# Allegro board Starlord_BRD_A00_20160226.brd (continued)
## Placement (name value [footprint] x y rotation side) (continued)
HS2  STFSR158R113H62-GP  [STFSR158R113H62]  174.7 89.86 0 top
HS3  STFSR158R113H62-GP  [STFSR158R113H62]  174.7 75.98 0 top
IOBD1  IPEX-CON50-1-GP  [20455-050E-76]  171.7 46.46 270 bottom
KBBD1  STAR-CON44-GP  [51540-04401-W01]  139.3 14.97 180 bottom
KBC24  MEC1404-NU-D0-1-GP-U  [TQFP128J16H48]  191.01 36.44 270 top
LCD1  IPEX-CON40-3-GP  [20455-040E-12]  88.7 97.71 0 bottom
NOREF  -  [unnamed]  69.91 -7.48 0 top
NOREF#2  -  [unnamed]  207.95 -120.53 0 top
NOREF#3  *  [unnamed]  232.84 113.08 0 top
NOREF#4  *  [unnamed]  196.87 17.19 0 top
NOREF#5  -  [#2]  160.17 12.82 0 top
NOREF#6  -  [unnamed]  169.35 102.57 0 top
NOREF#7  -  [#2]  1.7 -16.29 0 top
NOREF#8  -  [#2]  8.38 114.65 180 top
NOREF#9  -  [unnamed]  234.17 -121.61 0 top
NOREF#10  -  [unnamed]  234.17 78.88 0 top
NOREF#11  -  [#2]  -24.49 -18.4 0 top
NOREF#12  *  [unnamed]  24.59 91.1 0 top
NOREF#13  *  [unnamed]  175.84 37.13 0 top
NOREF#14  -  [#2]  130.55 110.71 0 top
NOREF#15  -  [#2]  1.7 -16.29 0 top
NOREF#16  -  [unnamed]  162.44 -4.62 0 top
NOREF#17  -  [unnamed]  24.4 108.43 180 top
NOREF#18  -  [#2]  72.4 113.39 180 top
NOREF#19  -  [#2]  5.44 -59.82 180 top
NOREF#20  *  [unnamed]  18.76 109.51 0 top
NOREF#21  -  [#2]  218.92 -126.91 0 top
NOREF#22  -  [#2]  57.65 -94.26 180 top
NOREF#23  *  [unnamed]  199.82 8.25 0 top
NOREF#24  -  [#2]  1.7 -16.29 0 top
NOREF#25  -  [unnamed]  -1.22 -25.43 0 top
NOREF#26  -  [#2]  174.7 82.15 0 top
NOREF#27  -  [unnamed]  -1.82 -90.98 0 top
NOREF#28  -  [#2]  82.45 78.17 0 top
NOREF#29  -  [#2]  23.11 -33.27 90 top
NOREF#30  *  [unnamed]  229.22 -121.61 0 top
NOREF#31  -  [unnamed]  233.6 15.21 180 top
NOREF#32  -  [#2]  1.42 -23.53 270 top
NOREF#33  -  [#2]  238.35 48.11 270 top
NOREF#34  -  [unnamed]  -1.82 109.51 0 top
NOREF#35  -  [#2]  159.95 -125.49 0 top
NOREF#36  *  [unnamed]  4.88 7.66 0 top
NOREF#37  -  [unnamed]  4.44 4 0 top
NOREF#38  -  [#2]  1.7 -16.29 0 top
NOREF#39  -  [#2]  226.91 47.72 0 top
NOREF#40  -  [#2]  209.24 21.17 270 top
NOREF#41  *  [unnamed]  232.84 113.08 180 bottom
NOREF#42  -  [#2]  1.42 -40.29 90 bottom
NOREF#43  *  [unnamed]  229.22 -121.61 180 bottom
NOREF#44  -  [#2]  94.41 111.85 180 bottom
NOREF#45  *  [unnamed]  4.88 7.64 180 bottom
NOREF#46  *  [unnamed]  93.72 84.65 180 bottom
NOREF#47  *  [unnamed]  187.37 8.27 180 bottom
NOREF#48  *  [unnamed]  17.24 99.2 180 bottom
NOREF#49  *  [unnamed]  18.76 109.51 180 bottom
NOREF#50  *  [unnamed]  88.26 40.56 180 bottom
PC1001  SC22U6D3V3MX-1-GP  [C603H40]  124.66 98.64 180 top
PC1002  SC22U6D3V3MX-1-GP  [C603H40]  133.65 68.42 0 bottom
PC1003  SC22U6D3V3MX-1-GP  [C603H40]  140 63.97 0 top
PC1004  SC22U6D3V3MX-1-GP  [C603H40]  141.22 69.56 180 top
PC1005  SC22U6D3V3MX-1-GP  [C603H40]  122.1 56.86 0 top
PC1006  SC22U6D3V3MX-1-GP  [C603H40]  113.64 60.8 180 top
PC1007  SC22U6D3V3MX-1-GP  [C603H40]  114.91 60.8 180 top
PC1008  SC22U6D3V3MX-1-GP  [C603H40]  116.18 60.8 180 top
PC1009  SC22U6D3V3MX-1-GP  [C603H40]  132.74 62.98 180 bottom
PC1010  SC22U6D3V3MX-1-GP  [C603H40]  113.08 56.61 0 top
PC1011  SC22U6D3V3MX-1-GP  [C603H40]  114.35 56.61 0 top
PC1012  SC22U6D3V3MX-1-GP  [C603H40]  115.62 56.61 0 top
PC1013  SC22U6D3V3MX-1-GP  [C603H40]  116.89 56.61 0 top
PC1014  SC22U6D3V3MX-1-GP  [C603H40]  118.16 56.61 0 top
PC1015  SC22U6D3V3MX-1-GP  [C603H40]  110.49 56.61 0 top
PC1016  SC22U6D3V3MX-1-GP  [C603H40]  119.43 56.61 0 top
PC1017  SC22U6D3V3MX-1-GP  [C603H40]  120.7 56.61 0 top
PC1018  SC22U6D3V3MX-1-GP  [C603H40]  135.28 62.98 180 bottom
PC1019  SC22U6D3V3MX-1-GP  [C603H40]  134.01 62.98 180 bottom
PC1020  SC22U6D3V3MX-1-GP  [C603H40]  111.76 56.61 0 top
PC1021  SC22U6D3V3MX-1-GP  [C603H40]  112.32 60.8 180 top
PC1022  SC22U6D3V3MX-1-GP  [C603H40]  141.53 62.7 0 top
PC1023  SC22U6D3V3MX-1-GP  [C603H40]  137.29 63.97 0 top
PC1024  SC22U6D3V3MX-1-GP  [C603H40]  117.45 60.8 180 top
PC1025  SC22U6D3V3MX-1-GP  [C603H40]  118.72 60.8 180 top
PC1026  SC22U6D3V3MX-1-GP  [C603H40]  138.61 63.97 0 top
PC1027  SC22U6D3V3MX-1-GP  [C603H40]  134.92 68.42 0 bottom
PC1028  SC22U6D3V3MX-1-GP  [C603H40]  137.08 69.94 180 top
PC1029  SC22U6D3V3MX-1-GP  [C603H40]  138.48 69.94 180 top
PC1030  SC22U6D3V3MX-1-GP  [C603H40]  139.88 69.94 180 top
PC1031  SC22U6D3V3MX-1-GP  [C603H40]  141.53 62.7 180 bottom
PC1032  SC22U6D3V3MX-1-GP  [C603H40]  142.92 62.7 180 bottom
PC1034  SC22U6D3V3MX-1-GP  [C603H40]  142.92 62.7 0 top
PC1036  SC22U6D3V3MX-1-GP  [C603H40]  142.54 68.93 180 top
PC1037  SC22U6D3V3MX-1-GP  [C603H40]  118.67 68.39 270 top
PC1038  SC22U6D3V3MX-1-GP  [C603H40]  144.32 84.67 180 top
PC1039  SC22U6D3V3MX-1-GP  [C603H40]  138.48 79.37 0 top
PC1040  SC22U6D3V3MX-1-GP  [C603H40]  124 89.91 180 bottom
PC1041  SC22U6D3V3MX-1-GP  [C603H40]  118.62 63.85 0 top
PC1042  SC22U6D3V3MX-1-GP  [C603H40]  139.55 73.12 90 top
PC1043  SC22U6D3V3MX-1-GP  [C603H40]  118.67 69.69 270 top
PC1044  SC22U6D3V3MX-1-GP  [C603H40]  115.26 75 270 top
PC1045  SC22U6D3V3MX-1-GP  [C603H40]  124.2 95.14 0 bottom
PC1046  SC22U6D3V3MX-1-GP  [C603H40]  139.75 79.37 0 top
PC1047  SC22U6D3V3MX-1-GP  [C603H40]  118.46 70.96 270 top
PC1048  SC22U6D3V3MX-1-GP  [C603H40]  116.08 63.85 0 top
PC1049  SC22U6D3V3MX-1-GP  [C603H40]  119.89 63.85 0 top
PC1050  SC22U6D3V3MX-1-GP  [C603H40]  113.54 63.85 0 top
PC1051  SC22U6D3V3MX-1-GP  [C603H40]  139.55 74.51 90 top
PC1052  SC22U6D3V3MX-1-GP  [C603H40]  112.27 63.85 0 top
PC1053  SC22U6D3V3MX-1-GP  [C603H40]  141.02 79.37 0 top
PC1054  SC22U6D3V3MX-1-GP  [C603H40]  117.35 63.85 0 top
PC1055  SC22U6D3V3MX-1-GP  [C603H40]  142.29 79.37 0 top
PC1056  SC22U6D3V3MX-1-GP  [C603H40]  143.56 79.37 0 top
PC1057  SC22U6D3V3MX-1-GP  [C603H40]  144.83 79.37 0 top
PC1058  SC22U6D3V3MX-1-GP  [C603H40]  119.3 76.39 90 top
PC1059  SC22U6D3V3MX-1-GP  [C603H40]  121.16 63.85 0 top
PC1060  SC22U6D3V3MX-1-GP  [C603H40]  122.73 89.91 180 bottom
PC1061  SC22U6D3V3MX-1-GP  [C603H40]  115.24 73.14 270 top
PC1062  SC22U6D3V3MX-1-GP  [C603H40]  118.67 67.12 270 top
PC1063  SC22U6D3V3MX-1-GP  [C603H40]  119.3 73.88 90 top
PC1064  SC22U6D3V3MX-1-GP  [C603H40]  139.75 75.91 90 top
PC1065  SC22U6D3V3MX-1-GP  [C603H40]  118.67 65.85 270 top
PC1066  SC22U6D3V3MX-1-GP  [C603H40]  114.81 63.85 0 top
PC1067  SC22U6D3V3MX-1-GP  [C603H40]  123.24 98.64 180 top
PC1068  SC22U6D3V3MX-1-GP  [C603H40]  142.92 84.67 180 top
PC1069  SC22U6D3V3MX-1-GP  [C603H40]  139.6 86.96 90 top
PC1070  SC22U6D3V3MX-1-GP  [C603H40]  139.75 77.31 90 top
PC1071  SC22U6D3V3MX-1-GP  [C603H40]  120.57 50.51 0 top
PC1072  SC22U6D3V3MX-1-GP  [C603H40]  137.08 53.69 0 top
PC1073  SC22U6D3V3MX-1-GP  [C603H40]  119.3 50.51 0 top
PC1074  SC22U6D3V3MX-1-GP  [C603H40]  137.08 58 180 top
PC1075  SC22U6D3V3MX-1-GP  [C603H40]  138.35 53.69 0 top
PC1076  SC22U6D3V3MX-1-GP  [C603H40]  132.74 60.32 0 bottom
PC1077  SC22U6D3V3MX-1-GP  [C603H40]  134.03 60.29 0 bottom
PC1078  SC22U6D3V3MX-1-GP  [C603H40]  138.35 58 180 top
PC1101  DO NOT STUFF  [C603H40]  81.88 67.18 180 top
PC1102  SC22U6D3V3MX-1-GP  [C603H40]  110.29 66.39 180 top
PC1103  SC22U6D3V3MX-1-GP  [C603H40]  110.16 53.33 270 top
PC1104  DO NOT STUFF  [C603H40]  111.56 66.39 180 top
PC1105  SC22U6D3V3MX-1-GP  [C603H40]  96.09 18.66 270 bottom
PC1106  SC22U6D3V3MX-1-GP  [C603H40]  96.09 17.39 270 bottom
PC1107  SC10U6D3V3MX-GP  [C603H38]  83.72 60.74 0 top
PC1108  SC10U6D3V3MX-GP  [C603H38]  82.39 60.74 0 top
PC1109  SC10U6D3V3MX-GP  [C603H38]  83.44 52.84 0 top
PC1110  SCD1U25V2KX-GP  [C402H22]  82.17 52.84 0 top
PC1111  SCD1U25V2KX-GP  [C402H22]  81.28 52.84 0 top
PC1112  SCD1U25V2KX-GP  [C402H22]  81.16 60.8 0 top
PC1113  SCD1U25V2KX-GP  [C402H22]  84.03 66.83 180 top
PC1114  DO NOT STUFF  [C603H40]  80.49 67.18 180 top
PC1115  SC22U6D3V3MX-1-GP  [C603H40]  50.95 48.84 270 top
PC4301  SC1U50V3KX-GP  [C603H32]  21.54 76.24 0 top
PC4302  SCD1U50V3KX-GP  [C603H36]  22.83 76.24 0 top
PC4303  SCD01U50V2KX-1GP  [C402H22]  27 85.89 270 top
PC4304  DO NOT STUFF  [C402H22]  27 86.73 270 top
PC4305  DO NOT STUFF  [C402H22]  27 87.57 270 top
PC4306  SC10U25V3MX-GP  [C603H40]  26.92 84.85 270 top
PC4307  SCD15U10V2KX-GP  [C402H22]  24.05 83.81 270 bottom
PC4310  SC100P50V2JN-3GP  [C402H22]  42.21 71.34 180 top
PC4311  SC100P50V2JN-3GP  [C402H22]  37.36 72.76 270 top
PC4312  SCD1U25V2KX-GP  [C402H22]  47.93 85.06 270 top
PC4402  SCD1U25V2KX-GP  [C402H22]  147.39 33.9 0 bottom
PC4403  SC2200P50V2KX-2GP  [C402H22]  145.21 34.23 270 top
PC4404  SC2200P50V2KX-2GP  [C402H22]  145.24 35.12 270 top
PC4405  SC10U25V5KX-GP  [C805H56]  139.11 49.27 90 bottom
PC4406  SC10U25V5KX-GP  [C805H56]  140.18 46.22 180 bottom
PC4407  SC10U25V5KX-GP  [C805H56]  138.38 46.22 180 bottom
PC4408  SC10U25V5KX-GP  [C805H56]  139.11 51.15 90 bottom
PC4409  SCD1U25V2KX-GP  [C402H22]  141.5 46.32 180 bottom
PC4410  DO NOT STUFF  [C402H22]  143.18 46.33 180 bottom
PC4411  DO NOT STUFF  [C402H22]  142.34 46.32 180 bottom
PC4412  SC1U50V5ZY-1-GP-U  [C805H58]  144.14 40.05 0 bottom
PC4413  SC2D2U10V2KX-GP  [C402H22]  147.17 31.82 270 bottom
PC4414  SCD22U25V3KX-GP  [C603H40]  145.16 39.84 0 top
PC4415  SC10U25V5KX-GP  [C805H56]  155.95 31.69 270 bottom
PC4416  SCD1U50V3KX-GP  [C603H36]  156.08 36.87 270 bottom
PC4417  SC10U25V3MX-2-GP  [C603H40]  156.08 38.14 270 bottom
PC4418  SC10U25V5KX-GP  [C805H56]  155.95 33.52 270 bottom
PC4419  SCD1U25V2KX-GP  [C402H22]  153.08 31.08 90 bottom
PC4420  SCD1U25V2KX-GP  [C402H22]  141.22 39.77 270 top
PC4421  SC2200P50V2KX-2GP  [C402H22]  142.59 36.39 90 top
PC4422  SC2200P50V2KX-2GP  [C402H22]  141.78 34.46 0 top
PC4423  SC2K2P50V2JX-GP  [C402H22]  143.31 30.32 0 bottom
PC4424  SC2200P50V2KX-2GP  [C402H22]  142.42 30.32 0 bottom
PC4426  SCD22U25V3KX-GP  [C603H40]  148.79 36.41 90 bottom
PC4427  SC560P50V2KX-2GP  [C402H24]  137.49 32.78 90 bottom
PC4428  SC1U10V2KX-1GP  [C402H22]  142.14 38.83 270 top
PC4430  SC2200P50V2KX-2GP  [C402H22]  140.94 28.97 270 bottom
PC4431  SC1U10V2KX-1GP  [C402H22]  142.95 40.94 270 top
PC4432  SCD022U25V2KX-GP  [C402H22]  137.49 33.6 90 bottom
PC4433  SC10U25V5KX-GP  [C805H56]  155.95 35.32 270 bottom
PC4434  SC2200P50V2KX-2GP  [C402H22]  156.36 50.61 90 top
PC4435  SC10U25V5KX-GP  [C805H56]  158.3 30.6 0 bottom
PC4436  SC1KP50V2KX-1GP  [C402H22]  149.45 37.08 180 top
PC4437  SC1KP50V2KX-1GP  [C402H22]  146.66 37.76 0 bottom
PC4438  SC1U10V2KX-1GP  [C402H22]  135.74 30.6 0 bottom
PC4501  SCD1U25V2KX-GP  [C402H22]  157.48 61.94 90 bottom
PC4502  SC10U25V3MX-2-GP  [C603H40]  157.45 58.23 90 bottom
PC4503  SC10U25V3MX-2-GP  [C603H40]  157.45 60.85 90 bottom
PC4504  SC10U25V3MX-2-GP  [C603H40]  157.45 59.53 90 bottom
PC4505  SC10U25V3MX-2-GP  [C603H40]  93.19 107.03 0 top
PC4506  SCD1U25V2KX-GP  [C402H22]  158.21 55.31 180 bottom
PC4507  SC4D7U6D3V3KX-GP  [C603H36]  164.77 57.09 0 bottom
PC4508  DO NOT STUFF  [C402H22]  163.32 62.55 0 bottom
PC4509  SC22U6D3V5MX-2GP  [C805H58]  160.73 47.51 180 bottom
PC4510  SC22U6D3V5MX-2GP  [C805H58]  157.22 51.81 90 bottom
PC4511  SC22U6D3V5MX-2GP  [C805H58]  164.44 47.51 180 bottom
PC4512  DO NOT STUFF  [C805H58]  158.88 47.54 180 bottom
PC4513  SCD1U16V2KX-3GP  [C402H22]  157.21 53.18 90 bottom
PC4514  SC22U6D3V5MX-2GP  [C805H58]  108.21 111.09 0 bottom
PC4515  SC22U6D3V5MX-2GP  [C805H58]  110.26 100.02 180 bottom
PC4516  SC22U6D3V5MX-2GP  [C805H58]  110.04 111.09 0 bottom
PC4517  SC22U6D3V5MX-2GP  [C805H58]  113.73 111.09 0 bottom
PC4518  SCD1U16V2KX-3GP  [C402H22]  115.92 110.96 0 bottom
PC4519  SC10U25V3MX-2-GP  [C603H40]  94.59 107.03 0 top
PC4520  SC4D7U25V5KX-GP  [C805H54]  105.76 97.32 180 bottom
PC4521  SCD1U25V2KX-GP  [C402H22]  102.77 108.37 0 top
PC4522  SCD1U25V2KX-GP  [C402H22]  95.98 107.15 0 top
PC4523  SC10U25V3MX-2-GP  [C603H40]  91.79 107.03 0 top
PC4524  SC2D2U10V3KX-1GP  [C603H36]  102.59 102.1 0 top
PC4525  SC22U6D3V5MX-2GP  [C805H58]  162.61 47.51 180 bottom
PC4526  SC1KP50V2KX-1GP  [C402H22]  99.74 102.44 0 top
PC4527  SC22U6D3V5MX-2GP  [C805H58]  108.31 100.02 180 bottom
PC4528  SCD1U16V2KX-3GP  [C402H22]  115.06 110.96 0 bottom
PC4529  SC22U6D3V5MX-2GP  [C805H58]  111.87 111.09 0 bottom
PC4530  DO NOT STUFF  [C402H22]  94.29 103.22 0 top
PC4531  DO NOT STUFF  [C402H22]  97.56 99.48 90 top
PC4532  DO NOT STUFF  [C402H22]  164.16 62.17 0 bottom
PC4533  SC1KP50V2KX-1GP  [C402H22]  164.21 59.71 0 bottom
PC4601  SC1500P50V2KX-2GP  [C402H22]  154.02 100.58 180 top
PC4602  SCD015U25V2KX-GP  [C402H22]  162.08 95.01 90 bottom
PC4603  SC1KP50V2KX-1GP  [C402H22]  162.08 93.31 90 bottom
PC4604  SC15P50V2JN-2-GP  [C402H22]  159.66 94.45 90 top
PC4605  SC1KP50V2KX-1GP  [C402H22]  163.37 93.34 0 bottom
PC4606  SCD01U50V2KX-1GP  [C402H22]  161.67 97.12 0 bottom
PC4607  SCD01U50V2KX-1GP  [C402H22]  162.5 97.13 0 bottom
PC4608  SC1KP50V2KX-1GP  [C402H22]  162.08 91.61 90 bottom
PC4609  SC220P50V2KX-3GP  [C402H22]  161.72 97.25 180 top
PC4610  SCD1U25V2KX-GP  [C402H22]  160.07 102.61 270 bottom
PC4611  SC1KP50V2KX-1GP  [C402H22]  160.78 89.22 180 bottom
PC4612  SC2200P50V2KX-2GP  [C402H22]  159.15 89.22 0 bottom
PC4613  SC470P50V2KX-3GP  [C402H22]  157.71 97.5 0 top
PC4614  SC470P50V2KX-3GP  [C402H22]  158.93 88.74 0 top
PC4615  SC470P50V2KX-3GP  [C402H22]  157.69 92.35 0 top
PC4616  SCD01U50V2KX-1GP  [C402H22]  156.28 101.92 90 bottom
PC4617  SC10P50V2JN-4GP  [C402H22]  157.63 89.17 270 top
PC4618  SC2200P50V2KX-2GP  [C402H22]  156.26 88.74 180 top
PC4619  SC15P50V2JN-2-GP  [C402H22]  154.34 98.04 0 top
PC4620  SC1KP50V2KX-1GP  [C402H22]  156.24 88.63 90 bottom
PC4621  SC100P50V2JN-3GP  [C402H22]  156.24 89.52 90 bottom
PC4622  SCD033U25V2KX-GP  [C402H22]  153.73 88.97 270 bottom
PC4623  SC1KP50V2KX-1GP  [C402H22]  153.72 100.54 180 bottom
PC4624  SCD033U25V2KX-GP  [C402H22]  154.42 90.01 270 top
PC4625  SC1KP50V2KX-1GP  [C402H22]  152.22 101.82 90 bottom
PC4626  SCD01U50V2KX-1GP  [C402H22]  155.96 92.71 180 top
PC4627  SC1KP50V2KX-1GP  [C402H22]  150.95 102.25 0 bottom
PC4628  SCD1U25V2KX-GP  [C402H22]  153.08 98.31 90 top
PC4629  SCD01U50V2KX-1GP  [C402H22]  153.54 91.57 90 top
PC4630  SCD1U25V2KX-GP  [C402H22]  155.07 92.71 180 top
PC4631  SC1U10V2KX-1GP  [C402H22]  153.8 92.4 90 top
PC4632  SC1KP50V2KX-1GP  [C402H22]  159.66 95.27 270 top
PC4633  SC1KP50V2KX-1GP  [C402H22]  155.23 98.04 0 top
PC4634  SCD022U25V2KX-GP  [C402H22]  156.28 101.11 90 bottom
PC4701  SC10U25V5KX-GP  [C805H56]  159.54 70.24 0 bottom
PC4702  SC10U25V5KX-GP  [C805H56]  161.44 70.24 0 bottom
PC4703  SC10U25V5KX-GP  [C805H56]  162 66.29 180 bottom
PC4704  SC10U25V5KX-GP  [C805H56]  157.68 70.24 0 bottom
PC4705  SC10U25V5KX-GP  [C805H56]  160.09 66.29 180 bottom
PC4706  SCD22U25V3KX-GP  [C603H40]  157.81 66.06 90 bottom
PC4707  SC2D2U10V2KX-GP  [C402H22]  150.47 62.75 180 bottom
PC4708  SC1U10V2KX-1GP  [C402H22]  151.74 62.25 90 bottom
PC4709  DO NOT STUFF  [C402H22]  145.85 62.58 90 bottom
PC4710  SCD1U25V2KX-GP  [C402H22]  156.26 70.39 0 bottom
PC4802  SC10U25V5KX-GP  [C805H56]  159.97 85.72 0 bottom
PC4803  SC10U25V5KX-GP  [C805H56]  159.69 81.88 180 bottom
PC4804  SC10U25V5KX-GP  [C805H56]  161.87 85.72 0 bottom
PC4805  SC10U25V5KX-GP  [C805H56]  161.59 81.88 180 bottom
PC4806  SC10U25V5KX-GP  [C805H56]  158.06 85.72 0 bottom
PC4807  SC2D2U10V2KX-GP  [C402H22]  153.02 78.96 90 bottom
PC4808  SC1U10V2KX-1GP  [C402H22]  152.18 78.15 270 bottom
PC4809  SCD22U25V3KX-GP  [C603H40]  157.4 82.13 90 bottom
PC4810  DO NOT STUFF  [C402H22]  147.06 88.64 270 bottom
PC4811  SCD1U25V2KX-GP  [C402H22]  156.64 85.75 0 bottom
PC4812  SCD1U25V2KX-GP  [C402H22]  145.08 94.63 180 bottom
PC4814  DO NOT STUFF  [C402H22]  135.08 99.13 90 bottom
PC4820  SC10U25V5KX-GP  [C805H56]  147.6 99.36 270 bottom
PC4827  SC10U25V5KX-GP  [C805H56]  143.05 99.18 90 bottom
PC4828  SC10U25V5KX-GP  [C805H56]  146.43 94.58 180 bottom
PC4829  SC10U25V5KX-GP  [C805H56]  148.33 94.58 180 bottom
PC4830  SC10U25V5KX-GP  [C805H56]  147.62 97.53 270 bottom
PC4845  SCD22U25V3KX-GP  [C603H40]  146.23 91.91 90 bottom
PC4846  SC2D2U10V2KX-GP  [C402H22]  142.25 89.98 90 bottom
PC4847  SC1U10V2KX-1GP  [C402H22]  141.23 89.15 270 bottom
PC5001  SC2D2U10V3KX-1GP  [C603H36]  153.31 51.5 90 bottom
PC5002  SCD1U25V2KX-GP  [C402H22]  150.29 58.96 180 bottom
PC5008  SCD22U25V3KX-GP  [C603H40]  150.42 54.86 180 bottom
PC5027  SC10U25V5KX-GP  [C805H56]  153.64 59.15 180 bottom
PC5029  SC10U25V5KX-GP  [C805H56]  151.74 59.15 180 bottom
PC5031  SC2200P50V2KX-2GP  [C402H22]  148.64 57.78 90 top
PC5101  SC22U6D3V5MX-2GP  [C805H58]  34.59 3.65 180 bottom
PC5102  SCD1U16V2KX-3GP  [C402H22]  37.87 3.5 180 bottom
PC5103  SC22U6D3V5MX-2GP  [C805H58]  33.96 8.09 90 bottom
PC5104  SC22U6D3V5MX-2GP  [C805H58]  36.5 3.65 180 bottom
PC5105  SC22U6D3V5MX-2GP  [C805H58]  33.96 6.19 90 bottom
PC5106  DO NOT STUFF  [C805H56]  53.39 8.04 180 bottom
PC5107  SCD01U50V2KX-1GP  [C402H22]  52.07 10.1 270 bottom
PC5108  SC10U25V5KX-GP  [C805H56]  51.59 8.04 180 bottom
PC5110  SC1U10V2KX-1GP  [C402H22]  47.95 2.8 180 bottom
PC5111  SC1U10V2KX-1GP  [C402H22]  47.09 12.11 270 bottom
PC5112  SC330P50V2KX-3GP  [C402H22]  50.16 2.34 270 bottom
PC5113  SC2D2U10V3KX-1GP  [C603H36]  46.02 3.14 180 bottom
PC5114  SC22U6D3V5MX-2GP  [C805H58]  37.23 10.56 180 bottom
PC5115  SC10U6D3V3MX-GP  [C603H38]  42.72 8.22 270 bottom
PC5116  SCD1U16V2KX-3GP  [C402H22]  42.37 13.89 90 bottom
PC5117  SCD1U25V2KX-GP  [C402H22]  44.78 8.55 180 bottom
PC5118  SCD1U16V2KX-3GP  [C402H22]  41.07 8.47 0 bottom
PC5119  DO NOT STUFF  [C402H22]  46.33 13.02 270 bottom
PC5120  DO NOT STUFF  [C402H22]  46.33 14.65 270 bottom
PC5138  DO NOT STUFF  [C402H22]  53.03 2.76 180 bottom
PC5201  SC22U6D3V3MX-1-GP  [C603H40]  88.06 7.71 90 bottom
PC5202  SC1U10V2KX-1GP  [C402H22]  100.4 9.34 270 bottom
PC5203  SC22U6D3V3MX-1-GP  [C603H40]  88.06 6.32 90 bottom
PC5204  SCD1U25V2KX-GP  [C402H22]  100.51 4.16 0 top
PC5205  SC22U6D3V3MX-1-GP  [C603H40]  88.82 3.01 180 bottom
PC5206  SC22U6D3V3MX-1-GP  [C603H40]  88.06 4.92 90 bottom
PC5208  SCD1U25V2KX-GP  [C402H22]  89.91 3.12 180 bottom
PC5209  SC10U25V5KX-GP  [C805H56]  109.8 3.88 180 bottom
PC5210  SC10U25V5KX-GP  [C805H56]  107.9 3.88 180 bottom
PC5211  SC10U25V5KX-GP  [C805H56]  108.38 6.8 0 bottom
PC5212  SC220P50V2KX-3GP  [C402H22]  103.81 9.11 0 top
PC5213  SCD01U50V2KX-1GP  [C402H22]  100.4 8.5 270 bottom
PC5214  SCD1U50V3KX-GP  [C603H36]  106.3 3.62 180 bottom
PC5215  SC1KP50V2KX-1GP  [C402H22]  104.19 9.36 0 bottom
PC5216  SC10U25V5KX-GP  [C805H56]  106.5 6.8 0 bottom
PC5401  SC1U10V2KX-1GP  [C402H22]  66.88 14.19 270 bottom
PC5402  SC10U6D3V5KX-1GP  [C805H54]  54.76 12.95 180 bottom
PC5403  SC10U6D3V3MX-GP  [C603H38]  66.88 15.59 270 bottom
PC5404  DO NOT STUFF  [C805H58]  52.86 12.95 180 bottom
PC5405  SC68P50V2JN-1GP  [C402H22]  57.02 13.61 180 bottom
PC5406  DO NOT STUFF  [C402H22]  62.91 9.49 180 bottom
PC5407  DO NOT STUFF  [C402H22]  54.51 4.16 90 bottom
PC5408  SC1U10V2KX-1GP  [C402H22]  58.67 9.49 0 bottom
PC5409  SC1U10V2KX-1GP  [C402H22]  57.83 9.49 0 bottom
PC5410  SC1U10V2KX-1GP  [C402H22]  43.23 96.1 180 bottom
PC5411  SC68P50V2JN-1GP  [C402H22]  46.02 99.66 90 top
PC5412  SC22U6D3V5MX-2GP  [C805H58]  48.31 101.69 0 bottom
PC5413  SC10U6D3V5KX-1GP  [C805H54]  50.11 101.7 0 bottom
PC5414  SC10U6D3V3MX-GP  [C603H38]  44.88 96.36 270 bottom
PC5427  SCD1U16V2KX-3GP  [C402H22]  40.18 95.6 180 bottom
PD4301  SD103AWS-2-GP  [SOD323AKH38]  23.04 78.45 90 top
PD4302  LBAV99LT1G-1-GP  [SOT23-2D4-312H44]  16.91 70.7 180 bottom
PD4303  L30ESD24VC3-2-GP  [SOT23-2D4-312H60]  15.87 79.85 180 bottom
PD4304  DO NOT STUFF  [SOD123FLAKH40]  160.55 31.16 180 bottom
PD4305  RB751V-40-2-GP  [SOD323AKH38]  28.65 89.04 270 top
PD4306  RB751V-40-2-GP  [SOD323AKH38]  29.77 74.64 270 top
PD4401  RB751VM-40TE-17-GP  [SOD323-2513AKH36]  148.84 40.28 90 bottom
PD4402  RB751VM-40TE-17-GP  [SOD323-2513AKH36]  149.48 39.74 270 top
PD4404  L1SS355T1G-GP  [SOD323AKH44]  147.04 26.79 180 bottom
PD4405  RB751VM-40TE-17-GP  [SOD323-2513AKH36]  151.12 36.03 0 bottom
PD4406  RB751VM-40TE-17-GP  [SOD323-2513AKH36]  150.01 32.86 270 bottom
PD4407  RB751VM-40TE-17-GP  [SOD323-2513AKH36]  153.38 34.13 180 bottom
PD4409  RB751V-40-2-GP  [SOD323AKH38]  157.66 54.5 0 top
PD4411  RB751V-40-2-GP  [SOD323AKH38]  155.6 54.48 0 top
PG4401  DO NOT STUFF  [GAP-CLOSE-PWR-3]  142.09 30.4 270 top
PG4402  GAP-CLOSE-PWR-6-GP  [GAP-CLOSE-PWR]  39.04 85.06 0 top
PG4403  GAP-CLOSE-PWR-6-GP  [GAP-CLOSE-PWR]  39.04 86.83 0 top
PG4404  DO NOT STUFF  [GAP-CLOSE-PWR]  141.73 50.99 90 top
PG4405  DO NOT STUFF  [GAP-CLOSE-PWR]  141.98 51.02 90 bottom
PG4406  DO NOT STUFF  [GAP-CLOSE-PWR]  141.22 51.02 90 bottom
PG4407  DO NOT STUFF  [GAP-CLOSE-PWR]  140.97 50.99 90 top
PG4408  DO NOT STUFF  [GAP-CLOSE-PWR-3]  144.7 32.35 180 top
PG4409  GAP-CLOSE-PWR-6-GP  [GAP-CLOSE-PWR]  145.01 30.4 90 top
PG4410  GAP-CLOSE-PWR-6-GP  [GAP-CLOSE-PWR]  144.04 30.4 90 top
PG4412  GAP-CLOSE-PWR-6-GP  [GAP-CLOSE-PWR]  152.07 41.57 180 bottom
PG4413  GAP-CLOSE-PWR-6-GP  [GAP-CLOSE-PWR]  152.07 39.82 180 bottom
PG4414  DO NOT STUFF  [GAP-CLOSE-PWR-3]  141.04 30.4 270 top
PG4415  DO NOT STUFF  [GAP-CLOSE-PWR-3]  140.59 30.12 270 bottom
PG4419  DO NOT STUFF  [GAP-CLOSE-PWR-3]  143.08 30.45 270 top
PG4501  DO NOT STUFF  [GAP-CLOSE-PWR-3]  90.22 107.66 0 bottom
PG4502  DO NOT STUFF  [GAP-CLOSE-PWR-3]  90.22 108.42 0 bottom
PG4503  DO NOT STUFF  [GAP-CLOSE-PWR-3]  90.22 109.19 0 bottom
PG4504  DO NOT STUFF  [GAP-CLOSE-PWR-3]  90.22 109.19 0 top
PG4505  DO NOT STUFF  [GAP-CLOSE-PWR-3]  90.22 108.42 0 top
PG4506  DO NOT STUFF  [GAP-CLOSE-PWR-3]  90.22 107.66 0 top
PG4507  DO NOT STUFF  [GAP-CLOSE-PWR-3]  114.98 106.87 0 top
PG4508  DO NOT STUFF  [GAP-CLOSE-PWR-3]  114.98 106.11 0 top
PG4509  DO NOT STUFF  [GAP-CLOSE-PWR-3]  114.98 105.35 0 top
PG4510  DO NOT STUFF  [GAP-CLOSE-PWR-3]  114.98 104.59 0 top
PG4511  DO NOT STUFF  [GAP-CLOSE-PWR-3]  114.98 106.87 0 bottom
PG4512  DO NOT STUFF  [GAP-CLOSE-PWR-3]  114.98 106.11 0 bottom
PG4513  DO NOT STUFF  [GAP-CLOSE-PWR-3]  114.98 105.35 0 bottom
PG4514  DO NOT STUFF  [GAP-CLOSE-PWR-3]  114.98 104.59 0 bottom
PG4515  DO NOT STUFF  [GAP-CLOSE-PWR-3]  160.09 62.48 270 top
PG4516  DO NOT STUFF  [GAP-CLOSE-PWR-3]  159.33 62.48 270 top
PG4517  DO NOT STUFF  [GAP-CLOSE-PWR-3]  159.99 62.48 270 bottom
PG4518  DO NOT STUFF  [GAP-CLOSE-PWR-3]  159.23 62.48 270 bottom
PG4519  DO NOT STUFF  [GAP-CLOSE-PWR-3]  165.23 50.21 0 top
PG4520  DO NOT STUFF  [GAP-CLOSE-PWR-3]  165.23 49.45 0 top
PG4521  DO NOT STUFF  [GAP-CLOSE-PWR-3]  165.23 50.97 0 bottom
PG4522  DO NOT STUFF  [GAP-CLOSE-PWR-3]  165.23 50.21 0 bottom
PG4523  DO NOT STUFF  [GAP-CLOSE-PWR-3]  165.23 49.45 0 bottom
PG4524  DO NOT STUFF  [GAP-CLOSE-PWR-3]  165.23 50.97 0 top
PG4527  DO NOT STUFF  [GAP-CLOSE-PWR-3]  106.5 110.58 0 bottom
PG4528  DO NOT STUFF  [GAP-CLOSE-PWR-3]  101.45 102.63 270 top
PG4529  DO NOT STUFF  [GAP-CLOSE-PWR-3]  93.57 105.38 0 top
PG4530  DO NOT STUFF  [GAP-CLOSE-PWR-3]  164.97 52.16 270 bottom
PG4531  DO NOT STUFF  [GAP-CLOSE-PWR-3]  162.84 59.76 90 top
PG4532  DO NOT STUFF  [GAP-CLOSE-PWR-3]  162.81 58.16 90 top
PG4601  DO NOT STUFF  [GAP-CLOSE-PWR-3]  153.13 99.48 90 top
PG4707  DO NOT STUFF  [GAP-CLOSE-PWR-3]  146.61 67.95 0 bottom
PG4708  DO NOT STUFF  [GAP-CLOSE-PWR-3]  144.5 67.91 180 bottom
PG4808  DO NOT STUFF  [GAP-CLOSE-PWR-3]  146.86 82.43 0 bottom
PG4809  DO NOT STUFF  [GAP-CLOSE-PWR-3]  144.57 82.43 180 bottom
PG4815  DO NOT STUFF  [GAP-CLOSE-PWR-3]  135.74 94.52 0 bottom
PG4816  DO NOT STUFF  [GAP-CLOSE-PWR-3]  133.45 94.52 180 bottom
PG5021  GAP-CLOSE-PWR-3-GP  [GAP-CLOSE-PWR-3]  140.89 57.12 0 bottom
PG5022  GAP-CLOSE-PWR-3-GP  [GAP-CLOSE-PWR-3]  138.61 57.12 180 bottom
PG5023  -  [GAP-CLOSE-PWR]  154.65 61.92 0 bottom
PG5024  -  [GAP-CLOSE-PWR]  154.65 61.15 0 bottom
PG5025  -  [GAP-CLOSE-PWR]  134.29 54.07 0 bottom
PG5026  -  [GAP-CLOSE-PWR]  134.29 54.83 0 bottom
PG5027  -  [GAP-CLOSE-PWR]  134.29 55.59 0 bottom
PG5028  -  [GAP-CLOSE-PWR]  134.29 56.35 0 bottom
PG5029  -  [GAP-CLOSE-PWR]  134.29 57.12 0 bottom
PG5030  -  [GAP-CLOSE-PWR]  134.29 57.88 0 bottom
PG5031  -  [GAP-CLOSE-PWR]  134.29 58.64 0 bottom
PG5101  DO NOT STUFF  [GAP-CLOSE-PWR-3]  50.75 10.71 270 bottom
PG5102  DO NOT STUFF  [GAP-CLOSE-PWR-3]  35.76 9.85 90 bottom
PG5103  DO NOT STUFF  [GAP-CLOSE-PWR-3]  49.99 10.71 270 bottom
PG5104  DO NOT STUFF  [GAP-CLOSE-PWR-3]  49.22 10.71 270 bottom
PG5106  DO NOT STUFF  [GAP-CLOSE-PWR-3]  34.24 9.85 90 top
PG5107  DO NOT STUFF  [GAP-CLOSE-PWR-3]  50.75 10.71 270 top
PG5108  DO NOT STUFF  [GAP-CLOSE-PWR-3]  49.99 10.71 270 top
PG5109  DO NOT STUFF  [GAP-CLOSE-PWR-3]  35 9.85 90 bottom
PG5110  DO NOT STUFF  [GAP-CLOSE-PWR-3]  49.22 10.71 270 top
PG5111  DO NOT STUFF  [GAP-CLOSE-PWR-3]  34.24 9.85 90 bottom
PG5112  DO NOT STUFF  [GAP-CLOSE-PWR-3]  35 9.85 90 top
PG5113  DO NOT STUFF  [GAP-CLOSE-PWR-3]  48.84 2.68 90 bottom
PG5114  DO NOT STUFF  [GAP-CLOSE-PWR-3]  35.76 9.85 90 top
PG5120  DO NOT STUFF  [GAP-CLOSE-PWR-3]  36.63 13.18 90 bottom
PG5121  DO NOT STUFF  [GAP-CLOSE-PWR-3]  37.39 13.18 90 bottom
PG5201  DO NOT STUFF  [GAP-CLOSE-PWR]  89.81 9.06 90 bottom
PG5204  DO NOT STUFF  [GAP-CLOSE-PWR]  90.47 9.08 90 top
PG5206  DO NOT STUFF  [GAP-CLOSE-PWR]  86.66 9.08 90 top
PG5207  DO NOT STUFF  [GAP-CLOSE-PWR]  87.53 9.06 90 bottom
PG5208  DO NOT STUFF  [GAP-CLOSE-PWR]  89.05 9.06 90 bottom
PG5209  DO NOT STUFF  [GAP-CLOSE-PWR]  88.29 9.06 90 bottom
PG5210  DO NOT STUFF  [GAP-CLOSE-PWR]  109.75 7.08 270 bottom
PG5211  DO NOT STUFF  [GAP-CLOSE-PWR]  87.43 9.08 90 top
PG5212  DO NOT STUFF  [GAP-CLOSE-PWR]  110.51 7.08 270 bottom
PG5213  DO NOT STUFF  [GAP-CLOSE-PWR]  88.19 9.08 90 top
PG5214  DO NOT STUFF  [GAP-CLOSE-PWR]  111.28 7.08 270 bottom
PG5215  DO NOT STUFF  [GAP-CLOSE-PWR]  89.71 9.08 90 top
PG5216  DO NOT STUFF  [GAP-CLOSE-PWR]  88.95 9.08 90 top
PG5223  GAP-CLOSE-PWR-6-GP  [GAP-CLOSE-PWR]  102.54 9.24 180 top
PG5404  DO NOT STUFF  [GAP-CLOSE-PWR]  56.89 10.18 90 bottom
PG5405  DO NOT STUFF  [GAP-CLOSE-PWR]  51.99 15.64 180 bottom
PG5406  DO NOT STUFF  [GAP-CLOSE-PWR]  51.99 16.4 180 bottom
PG5407  DO NOT STUFF  [GAP-CLOSE-PWR]  51.99 14.88 180 bottom
PG5408  DO NOT STUFF  [GAP-CLOSE-PWR-3]  50.6 99.71 0 bottom
PG5409  DO NOT STUFF  [GAP-CLOSE-PWR-3]  50.6 98.95 0 bottom
PL4401  COIL-4D7UH-33-GP  [L7066-1830-UH119]  148.92 47.01 270 bottom
PL4501  COIL-1D5UH-43-GP  [L4947-1015H119]  161.59 52.54 180 bottom
PL4502  IND-1UH-94-GP-U  [L686647-127318H119]  107.72 105.86 90 bottom
PL4701  COIL-D15UH-2-GP  [L7366-1930H158]  145.62 67.99 90 bottom
PL4801  COIL-D15UH-2-GP  [L7366-1930H158]  145.72 82.56 90 bottom
PL4802  COIL-D15UH-2-GP  [L7366-1930H158]  134.59 94.39 90 bottom
PL5001  COIL-D47UH-6-GP  [L7066-1830-UH119]  139.75 57.04 90 bottom
PL5101  COIL-1UH-73-GP  [L4947-1115H119]  41.83 4.66 90 bottom
PL5201  IND-1UH-94-GP-U  [L686647-127318H119]  94.92 5.55 90 bottom
PQ4301  DMN5L06K-7-GP  [SOT23DGS2D4H48]  16.03 75.73 180 bottom
PQ4302  CH3904PT-GP  [SOT23CBE2D6H46]  22.96 73.17 270 bottom
PQ4304  LMUN5212T1G-GP  [SOT323CBE2D2H40]  19.84 77.41 270 bottom
PQ4305  LTA024EUB-FS8-GP  [SC70-2D2-312H44]  19.43 73.88 0 bottom
PQ4306  2N7002KDW-GP  [SOT-363H44]  23.42 78.01 0 bottom
PQ4307  2N7002KDW-GP  [SOT-363H44]  36.88 70.81 90 top
PQ4308  2N7002KDW-GP  [SOT-363H44]  29.92 70.58 0 top
PQ4309  2N7002KDW-GP  [SOT-363H44]  45.79 88.84 270 top
PQ4310  2N7002KDW-GP  [SOT-363H44]  33.3 70.81 90 top
PQ4311  2N7002KDW-GP  [SOT-363H44]  42.16 88.84 90 top
PQ4405  2N7002KDW-GP  [SOT-363H44]  138.3 30.04 270 bottom
PQ4408  MMBT3906-4-GP  [SOT23CBE2D4H44]  144.14 27.47 270 bottom
PQ4415  2N7002KDW-GP  [SOT-363H44]  139.9 39.39 270 bottom
PR4302  15KR2F-GP  [R402H16]  19.53 74.87 180 top
PR4303  10KR2J-3-GP  [R402H16]  17.04 73.24 270 bottom
PR4304  2K2R2J-2-GP  [R402H16]  15.26 73.24 270 bottom
PR4305  33R2J-2-GP  [R402H16]  17.37 74.36 90 top
PR4306  DO NOT STUFF  [R402H16]  17.37 75.25 270 top
PR4307  240KR3-GP  [R603H22]  24.1 76.24 0 top
PR4308  47KR2F-GP  [R402H16]  23.7 74.62 270 top
PR4309  100KR2J-1-GP  [R402H16]  18.64 74.87 0 top
PR4310  1KR2J-1-GP  [R402H16]  43.13 91.38 180 top
PR4311  100KR2F-L1-GP  [R402H16]  31.27 90.49 270 top
PR4312  470KR2F-GP  [R402H16]  23.93 82.13 270 top
PR4313  71K5R2F-1-GP  [R402H16]  22.15 82.13 270 top
PR4314  3K3R6J-GP  [R1206H28]  23.09 80.61 270 top
PR4315  18K7R2F-GP  [R402H16]  29.54 90.49 90 top
PR4316  20KR2J-L2-GP  [R402H16]  27.02 83.81 270 top
PR4317  -  [0R0603-PAD]  17.16 78.3 270 top
PR4318  100KR2J-1-GP  [R402H16]  34.59 88.61 270 top
PR4319  100KR2F-L1-GP  [R402H16]  39.62 72.41 270 top
PR4320  240KR2F-L-GP  [R402H16]  26.97 69.31 180 top
PR4321  47KR2F-GP  [R402H16]  27.86 69.31 0 top
PR4322  10KR2F-2-GP  [R402H16]  39.62 71.52 270 top
PR4323  100KR2F-L1-GP  [R402H16]  39.52 69.54 270 top
PR4324  100KR2F-L1-GP  [R402H16]  47.98 89.53 0 top
PR4327  12K4R2F-GP  [R402H16]  32.31 74.39 180 top
PR4328  2K2R2J-2-GP  [R402H16]  30.92 73.16 270 top
PR4329  100KR2F-L1-GP  [R402H16]  29.01 95.42 90 bottom
PR4330  240KR2F-L-GP  [R402H16]  46.66 85.44 0 top
PR4331  124KR2F-GP  [R402H16]  30.61 94.4 180 bottom
PR4332  100KR2F-L1-GP  [R402H16]  35.66 72.76 90 top
PR4333  10KR2F-2-GP  [R402H16]  34.59 89.5 270 top
PR4334  240KR2F-L-GP  [R402H16]  27.33 95.42 90 bottom
PR4335  100KR2J-1-GP  [R402H16]  19.66 80.26 180 bottom
PR4336  680KR2J-GP  [R402H16]  40.89 71.59 180 top
PR4337  240KR2F-L-GP  [R402H16]  41.65 90.95 270 top
PR4338  100R2512J-1-GP  [R2512H28]  39.04 75.4 270 top
PR4339  64K9R2F-1-GP  [R402H16]  47.55 86.33 180 top
PR4401  1KR2F-3-GP  [R402H16]  141.53 30.32 0 bottom
PR4402  D01R3721F-GP-U  [R3720H40]  36.71 85.95 180 top
PR4403  100R5F-2-GP  [R805H24]  148.51 38.24 270 bottom
PR4407  2D2R5J-1-GP  [R805H24]  145.95 40.05 0 bottom
PR4408  300KR2F-GP  [R402H16]  147.17 32.63 90 bottom
PR4409  37K4R2F-1-GP  [R402H16]  147.22 30.98 270 bottom
PR4410  1KR2F-3-GP  [R402H16]  149.48 35.37 0 top
PR4411  2R2F-GP  [R402H16]  141.65 41.09 0 top
PR4412  4D7R3F-L-GP  [R603H22]  143.28 39.87 90 top
PR4413  100KR2F-L1-GP  [R402H16]  135.66 28.92 90 bottom
PR4414  2R2F-GP  [R402H16]  149.15 35.25 90 bottom
PR4415  D01R3721F-GP-U  [R3720H40]  154.35 40.71 180 bottom
PR4416  100R2F-L1-GP-U  [R402H14]  138.73 33.21 0 bottom
PR4420  10KR2F-2-GP  [R402H16]  137.18 35.32 180 bottom
PR4421  10KR2F-2-GP  [R402H16]  138.02 37 0 bottom
PR4422  100KR2F-L2-GP  [R402H16]  144.83 33.42 270 top
PR4423  100KR2F-L1-GP  [R402H16]  140.54 32.73 90 top
PR4424  100KR2F-L1-GP  [R402H16]  139.29 37.43 270 bottom
PR4430  -  [0R0402-PAD]  140.54 33.57 90 top
PR4431  100KR2J-1-GP  [R402H16]  147.24 30.14 90 bottom
PR4433  150KR2F-L-GP  [R402H16]  139.67 32.43 180 bottom
PR4436  DO NOT STUFF  [R402H16]  147.24 29.3 90 bottom
PR4437  49K9R2F-L-GP  [R402H16]  142.59 37.2 90 top
PR4438  10KR2F-2-GP  [R402H16]  145.95 30.32 180 bottom
PR4439  10KR2F-2-GP  [R402H16]  145.08 30.32 180 bottom
PR4442  470KR2J-L1-GP  [R402H15]  158.04 50.13 0 top
PR4443  300KR2F-L-GP  [R402H16]  143.13 33.04 90 top
PR4444  -  [0R0402-PAD]  149.15 34.43 270 bottom
PR4445  100KR2F-L2-GP  [R402H16]  144.19 30.32 180 bottom
PR4447  -  [0R0603-PAD]  146.45 39.84 180 top
PR4448  -  [0R0402-PAD]  140.84 41.09 180 top
PR4449  1KR2F-3-GP  [R402H16]  138 35.12 0 bottom
PR4450  10KR2F-2-GP  [R402H16]  134.82 30.6 180 bottom
PR4451  680KR2F-GP  [R402H16]  137.49 28.85 90 top
PR4455  -  [0R0402-PAD]  138.81 29.76 180 top
PR4458  -  [0R0402-PAD]  146.94 23.99 270 bottom
PR4462  -  [0R0402-PAD]  137.49 29.68 270 top
PR4463  DO NOT STUFF  [R402H16]  137.49 30.52 270 top
PR4471  100KR2F-L2-GP  [R402H16]  140.92 41.34 270 bottom
PR4501  -  [0R0603-PAD]  157.1 56.29 180 bottom
PR4502  -  [0R0603-PAD]  100.95 109.29 90 top
PR4503  DO NOT STUFF  [R402H16]  95.69 103.73 0 top
PR4504  -  [0R0402-PAD]  93.83 101.54 0 top
PR4505  100KR2J-1-GP  [R402H16]  161.95 59.73 180 top
PR4506  1KR2F-3-GP  [R402H16]  165.02 59.71 0 bottom
PR4507  1KR2F-3-GP  [R402H16]  100.57 102.28 180 top
PR4508  DO NOT STUFF  [R402H16]  162.51 62.55 0 bottom
PR4509  1KR2F-3-GP  [R402H16]  161.59 62.5 180 bottom
PR4510  100KR2J-1-GP  [R402H16]  93.53 104.49 270 top
PR4511  1KR2F-3-GP  [R402H16]  92.51 103.22 180 top
PR4512  DO NOT STUFF  [R402H16]  93.4 103.22 0 top
PR4513  1MR2J-1-GP  [R402H16]  97.56 100.3 90 top
PR4514  1MR2J-1-GP  [R402H16]  165 62.17 0 bottom
PR4515  -  [0R0402-PAD]  96.58 103.73 0 top
PR4516  -  [0R0402-PAD]  96.11 104.99 270 top
PR4530  DO NOT STUFF  [R402H16]  96.14 102.48 270 top
PR4551  348KR2F-GP  [R402H16]  97.92 101.55 0 top
PR4601  1KR2F-3-GP  [R402H16]  151.32 91.61 270 bottom
PR4602  1K5R2F-2-GP  [R402H16]  159.79 93.62 90 top
PR4604  -  [0R0402-PAD]  164.64 93.64 90 bottom
PR4605  825R2F-GP  [R402H16]  162.08 94.2 90 bottom
PR4606  NTC-100K-1-GP-U  [NTC-402H24-U]  139.37 61.43 90 bottom
PR4607  -  [0R0402-PAD]  164.64 92.77 90 bottom
PR4608  2K61R2F-1-GP  [R402H16]  162.07 92.45 90 bottom
PR4609  14K3R2F-GP  [R402H16]  164.35 96.56 270 bottom
PR4611  27K4R2F-GP  [R402H16]  159.66 96.08 270 top
PR4612  8K06R3F-AS-GP  [R603H22]  164.46 97.63 270 bottom
PR4613  93K1R2F-L-GP  [R402H16]  160.91 97.25 0 top
PR4614  DO NOT STUFF  [R402H16]  163.45 99.15 180 bottom
PR4615  20KR2F-L-GP  [R402H16]  158.1 93.62 270 top
PR4616  -  [0R0402-PAD]  163.9 91.94 90 bottom
PR4617  -  [0R0402-PAD]  162.09 89.68 90 bottom
PR4618  -  [0R0402-PAD]  162.09 88.85 90 bottom
PR4619  1KR2F-3-GP  [R402H16]  159.97 89.22 180 bottom
PR4621  45D3R2F-L-GP  [R402H16]  155.93 105.81 0 top
PR4622  DO NOT STUFF  [R402H16]  155.09 105.81 0 top
PR4623  100R2F-L1-GP-U  [R402H14]  158.77 102.99 180 bottom
PR4624  DO NOT STUFF  [R402H16]  154.25 105.81 0 top
PR4625  37D4R2F-GP  [R402H16]  159.82 89.63 0 top
PR4626  1KR2F-3-GP  [R402H16]  158.52 89.98 270 top
PR4627  8K06R3F-AS-GP  [R603H22]  156.64 104.36 0 bottom
PR4628  110KR2F-GP  [R402H16]  158.52 97.5 0 top
PR4629  14KR2F-GP  [R402H16]  156.28 102.73 90 bottom
PR4630  -  [0R0402-PAD]  162.18 99.53 270 bottom
PR4631  4K75R2F-1-GP  [R402H16]  157.63 88.31 270 top
PR4632  26K1R2F-2-GP  [R402H16]  156.81 92.66 0 top
PR4633  NTC-100K-1-GP-U  [NTC-402H24-U]  145.97 72.33 270 bottom
PR4634  NTC-220K-5-GP-U  [NTC-402H24-U]  143.05 87.09 270 bottom
PR4635  59KR2F-GP  [R402H16]  156.06 98.04 0 top
PR4636  2K49R2F-GP  [R402H16]  156.87 98.11 0 top
PR4637  48K7R3F-1-GP  [R603H22]  152.83 88.36 0 top
PR4638  165KR2F-GP  [R402H16]  156.23 87.8 90 bottom
PR4639  75KR2F-GP  [R402H16]  157.5 88.51 0 bottom
PR4640  12K4R2F-GP  [R402H16]  158.33 89.22 180 bottom
PR4641  73K2R3F-1-GP  [R603H22]  154.15 87.62 270 bottom
PR4642  1KR2F-3-GP  [R402H16]  153.73 89.78 270 bottom
PR4643  10R2F-L-GP  [R402H14]  154.84 88.73 0 top
PR4644  422R2F-2-GP  [R402H16]  152.88 100.55 0 bottom
PR4645  -  [0R0402-PAD]  152.45 102.71 90 bottom
PR4646  10R2F-L-GP  [R402H14]  152.09 87.88 90 bottom
PR4647  3K83R2F-GP  [R402H16]  152.07 100.55 0 bottom
PR4648  -  [0R0402-PAD]  152.45 103.52 90 bottom
PR4649  2K49R2F-GP  [R402H16]  151.25 100.55 0 bottom
PR4650  -  [0R0402-PAD]  151.1 98.21 270 bottom
PR4651  6K98R2F-GP  [R402H16]  153.97 88.68 0 top
PR4652  12K7R2F-GP  [R402H16]  151.1 99.03 270 bottom
PR4653  NTC-100K-1-GP-U  [NTC-402H24-U]  151.64 71.8 90 bottom
PR4654  6K98R2F-GP  [R402H16]  154.99 89.25 180 bottom
PR4655  -  [0R0402-PAD]  152.47 89.21 0 bottom
PR4656  NTC-100K-1-GP-U  [NTC-402H24-U]  149.53 86.96 270 bottom
PR4657  2D2R2F-GP  [R402H16]  150.41 92.67 270 bottom
PR4658  90K9R2F-GP  [R402H16]  153.71 95.84 270 top
PR4659  24KR2F-GP  [R402H16]  153.8 94.17 90 top
PR4660  19K1R2F-GP  [R402H16]  153.72 96.66 270 top
PR4661  12K7R2F-GP  [R402H16]  151.66 89.21 0 bottom
PR4663  10KR2F-2-GP  [R402H16]  153.08 97.49 270 top
PR4664  24KR2F-GP  [R402H16]  153.8 93.29 90 top
PR4665  49D9R2F-GP  [R402H16]  160.5 100.63 180 bottom
PR4666  -  [0R0402-PAD]  159.69 100.63 180 bottom
PR4667  10R2F-L-GP  [R402H14]  158.8 100.63 180 bottom
PR4668  100R2F-L1-GP-U  [R402H14]  157.88 100.52 0 bottom
PR4669  DO NOT STUFF  [R402H16]  153.36 105.81 0 top
PR4670  -  [0R0402-PAD]  162.18 98.64 270 bottom
PR4671  -  [0R0402-PAD]  158.53 92.37 180 top
PR4672  48K7R2F-2-GP  [R402H16]  153.72 95.01 270 top
PR4701  3D9R3-GP  [R603H22]  157.81 64.66 270 bottom
PR4702  2D2R2F-GP  [R402H16]  151.74 63.06 90 bottom
PR4703  DO NOT STUFF  [R805H24]  148.26 62.96 90 bottom
PR4704  -  [0R0402-PAD]  154.1 63.08 90 bottom
PR4802  3D9R3-GP  [R603H22]  157.4 80.74 270 bottom
PR4803  2D2R2F-GP  [R402H16]  151.34 78.96 90 bottom
PR4804  DO NOT STUFF  [R805H24]  146.96 87.31 90 bottom
PR4805  3D9R3-GP  [R603H22]  146.23 90.62 270 bottom
PR4806  2D2R2F-GP  [R402H16]  140.47 89.98 90 bottom
PR4807  DO NOT STUFF  [R805H24]  137.62 99.13 90 bottom
PR4808  -  [0R0402-PAD]  154.35 78.52 0 bottom
PR4809  0R2J-2-GP  [R402H16]  143.97 89.78 90 bottom
PR5013  2D2R3-1-U-GP  [R603H22]  152.32 56.2 90 bottom
PR5014  2D2R5F-2-GP  [R805H24]  146.33 57.8 90 top
PR5101  -  [0R0603-PAD]  47.47 10.15 90 bottom
PR5102  -  [0R0402-PAD]  47.12 2.81 180 bottom
PR5103  10KR2F-2-GP  [R402H16]  50.16 3.23 270 bottom
PR5104  10KR2F-2-GP  [R402H16]  51.41 2.76 180 bottom
PR5105  -  [0R0402-PAD]  52.35 4.44 90 bottom
PR5106  DO NOT STUFF  [R402H16]  52.22 2.76 0 bottom
PR5107  -  [0R0402-PAD]  52.35 5.33 90 bottom
PR5114  -  [0R0402-PAD]  46.33 13.83 90 bottom
PR5118  -  [0R0402-PAD]  47.09 11.27 270 bottom
PR5125  -  [0R0402-PAD]  44.63 14.65 270 bottom
PR5126  0R2J-2-GP  [R402H16]  46.35 15.49 90 bottom
PR5201  88K7R2F-GP  [R402H16]  103.63 6.44 180 top
PR5202  2K55R2F-GP  [R402H16]  104.7 9.11 0 top
PR5203  100KR2F-L1-GP  [R402H16]  105 9.36 0 bottom
PR5204  10KR2F-2-GP  [R402H16]  105.59 9.11 180 top
PR5207  0R2J-2-GP  [R402H16]  101.7 9.08 180 bottom
PR5208  100KR2J-1-GP  [R402H16]  99.95 8.98 0 top
PR5209  -  [0R0402-PAD]  100.79 8.98 0 top
PR5210  0R2J-2-GP  [R402H16]  102.94 9.47 90 bottom
PR5401  DO NOT STUFF  [R402H16]  62.08 9.49 180 bottom
PR5402  DO NOT STUFF  [R402H16]  66.14 13.02 90 bottom
PR5403  16K5R2F-2-GP  [R402H16]  56.13 13.61 180 bottom
PR5404  13K3R2F-L1-GP  [R402H16]  56.56 12.36 90 bottom
PR5405  -  [0R0402-PAD]  54.91 2.89 0 bottom
PR5406  0R2J-2-GP  [R402H16]  64.31 9.11 90 bottom
PR5407  0R2J-2-GP  [R402H16]  64.31 10 90 bottom
PR5408  -  [0R0402-PAD]  66.75 12.21 90 bottom
PR5409  47KR2J-2-GP  [R402H16]  39.29 95.6 180 bottom
PR5410  10KR2F-2-GP  [R402H16]  41.88 95.6 0 bottom
PR5417  -  [0R0402-PAD]  41.07 95.6 0 bottom
PR5419  29K4R2F-GP  [R402H16]  46.02 98.64 90 top
PR5420  13K7R2F-GP  [R402H16]  46.02 100.55 270 top
PT4701  SE330U2VDM-L-GP  [CT7343H83]  138.38 67.22 0 bottom
PT4801  SE330U2VDM-L-GP  [CT7343H83]  127.38 93.59 0 bottom
PT4802  DO NOT STUFF  [CT7343H83]  139.24 74.39 270 bottom
PT4803  SE330U2VDM-L-GP  [CT7343H83]  138.23 82.9 0 bottom
PT4805  SE33U25VM-11-GP  [CT7343H83]  144.98 103.09 270 bottom
PT4806  SE33U25VM-11-GP  [CT7343H83]  165.71 84.24 0 bottom
PU4301  SI7121DN-T1-GE3-GP  [PPAK-8P-2H45]  28.62 81.5 0 top
PU4302  SI7121DN-T1-GE3-GP  [PPAK-8P-2H45]  30.02 85.69 90 top
PU4303  SI7121DN-T1-GE3-GP  [PPAK-8P-2H45]  39.42 80.36 90 top
PU4304  SI7121DN-T1-GE3-GP  [PPAK-8P-2H45]  33.07 79.98 180 top
PU4305  SI7625DN-T1-GE3-GP  [PPAK-8P-2H45]  42.59 84.93 90 top
PU4306  SI7625DN-T1-GE3-GP  [PPAK-8P-2H45]  45.13 79.09 180 top
PU4401  ISL95521AHRZ-T-GP  [QFN32J4-G2D7H42]  143.18 34.66 0 bottom
PU4403  SI7121DN-T1-GE3-GP  [PPAK-8P-2H45]  155.73 45.81 0 bottom
PU4404  SIS412DN-T1-GE3-GP  [PPAK-8P-2H45]  144.09 48.81 90 top
PU4405  SIS412DN-T1-GE3-GP  [PPAK-8P-2H45]  145.64 44.39 270 top
PU4501  SY8286BRAC-GP  [QFN20Z3-G1D1H36]  161.26 58.46 270 bottom
PU4502  SY8288CRAC-GP  [QFN20Z3-G1D1H36]  99.67 105.88 0 top
PU4601  NCP81208MNTXG-4-GP  [LFQFN48J6-G4D6H40]  156.49 95.22 0 bottom
PU4701  NCP81382MNTXG-3-GP  [QFN36J4060-G2554H48]  153.08 67.28 0 bottom
PU4801  NCP81382MNTXG-3-GP  [QFN36J4060-G2554H48]  153.34 83.32 0 bottom
PU4802  NCP81382MNTXG-3-GP  [QFN36J4060-G2554H48]  141.98 94.56 0 bottom
PU5001  NCP81253MNTBG-1-GP  [LFDFN8G2-G1309H40]  153.21 53.69 90 bottom
PU5002  SIS412DN-T1-GE3-GP  [PPAK-8P-2H45]  147.83 59.76 90 bottom
PU5003  SIS412DN-T1-GE3-GP  [PPAK-8P-2H45]  146.3 55.29 270 bottom
PU5101  SY8288RAC-GP  [QFN20Z3-G1H36]  47.93 6.95 180 bottom
PU5102  APL5338XAI-TRG-GP  [MSOP10-G2D5H44]  41.93 11.42 90 bottom
PU5201  AOZ2262QI-10-GP-U  [QFN22G4-G2PH42]  102.54 4.92 180 bottom
PU5401  APL5930KAI-TRG-GP  [SOIC8-G3530H63]  61.39 13.55 90 bottom
PU5402  S-1339D15-M5001-GP  [SOT-23-5H52]  56.95 6.82 270 bottom
PU5403  APL5930KAI-TRG-GP  [SOIC8-G3530H63]  43.43 100.07 270 bottom
Q501  DMN5L06K-7-GP  [SOT23DGS2D4H48]  34.39 13.1 180 bottom
Q1701  2N7002KDW-GP  [SOT-363H44]  69.26 8.22 90 bottom
Q1702  2N7002KDW-GP  [SOT-363H44]  69.39 11.27 90 bottom
Q1801  2N7002KDW-GP  [SOT-363H44]  101.62 15.38 90 bottom
Q1802  2N7002K-2-GP  [SOT23DGS2D4H44]  65.1 3.9 180 bottom
Q2408  2N7002K-2-GP  [SOT23DGS2D4H44]  191.49 39.11 0 bottom
Q2414  2N7002K-2-GP  [SOT23DGS2D4H44]  187.27 35.12 180 bottom
Q2415  2N7002K-2-GP  [SOT23DGS2D4H44]  190.93 35.42 90 bottom
Q2416  2N7002KDW-GP  [SOT-363H44]  180.72 47.9 0 top
Q2505  2N7002K-2-GP  [SOT23DGS2D4H44]  73.07 9.62 90 bottom
Q2601  2N7002KDW-GP  [SOT-363H44]  135.05 36.16 180 bottom
Q2602  2N7002K-2-GP  [SOT23DGS2D4H44]  142.64 23.82 180 bottom
Q2603  CH3904PT-GP  [SOT23CBE2D6H46]  49.38 96.38 90 bottom
Q2604  2N7002KDW-GP  [SOT-363H44]  195.07 39.59 90 bottom
Q2605  2N7002KDW-GP  [SOT-363H44]  196.04 36.29 0 bottom
Q2701  2N7002K-2-GP  [SOT23DGS2D4H44]  21.77 28.44 270 bottom
Q2702  DMP2130L-7-GP  [SOT23DGS2D4H48]  21.66 24.88 90 bottom
Q4001  SSM3K15AMFV-GP-U  [SOT723DGS1D2H22]  105.1 90.54 0 bottom
Q4008  2N7002K-2-GP  [SOT23DGS2D4H44]  69.85 14.82 180 bottom
Q4009  DMP2130L-7-GP  [SOT23DGS2D4H48]  73.63 13.61 90 bottom
Q5704  2N7002K-2-GP  [SOT23DGS2D4H44]  19.56 60.32 0 bottom
Q6105  2N7002K-2-GP  [SOT23DGS2D4H44]  163.67 30.24 180 bottom
Q6401  RN2418-GP  [SOT23CBE2D6H62]  114.1 15.88 270 bottom
Q6402  RN2418-GP  [SOT23CBE2D6H62]  117.37 11.09 90 bottom
Q6501  P8503BMG-GP  [SOT23DGS2D8H56]  137.13 21.51 0 bottom
Q6502  DMP2130L-7-GP  [SOT23DGS2D4H48]  121.11 21.3 90 bottom
Q6503  2N7002K-2-GP  [SOT23DGS2D4H44]  122.15 17.59 0 bottom
Q6504  2N7002KDW-GP  [SOT-363H44]  133.78 21.56 180 bottom
Q6505  RN2418-GP  [SOT23CBE2D6H62]  147.39 21.51 90 bottom
Q7001  2N7002KDW-GP  [SOT-363H44]  123.29 9.16 90 bottom
R401  1KR2J-1-GP  [R402H16]  131.14 76.98 270 bottom
R402  51R2J-2-GP  [R402H16]  133.02 70.45 180 bottom
R403  499R2F-2-GP  [R402H16]  130.58 76.14 90 bottom
R404  100KR2J-1-GP  [R402H16]  121.11 14.82 180 bottom
R405  100KR2J-1-GP  [R402H16]  121.92 14.82 180 bottom
R406  51R2J-2-GP  [R402H16]  131.14 72.33 270 bottom
R407  51R2J-2-GP  [R402H16]  123.9 69.03 0 top
R408  51R2J-2-GP  [R402H16]  131.16 67.1 270 bottom
R409  51R2J-2-GP  [R402H16]  131.47 66.29 270 bottom
R410  0R2J-2-GP  [R402H16]  123.29 15.18 90 bottom
R412  49D9R2F-GP  [R402H16]  93.9 51.45 270 top
R413  49D9R2F-GP  [R402H16]  94.38 53.18 270 top
R414  49D9R2F-GP  [R402H16]  120.9 74.85 180 top
R415  49D9R2F-GP  [R402H16]  120.9 73.14 180 top
R416  51R2J-2-GP  [R402H16]  131.14 68.72 270 bottom
R417  1KR2J-1-GP  [R402H16]  131.16 67.91 270 bottom
R419  1KR2J-1-GP  [R402H16]  133.45 75.23 90 bottom
R421  51R2J-2-GP  [R402H16]  131.19 70.7 270 bottom
R422  51R2J-2-GP  [R402H16]  131.47 65.47 270 bottom
R423  51R2J-2-GP  [R402H16]  131.14 71.52 270 bottom
R501  121R2F-GP  [R402H16]  94.36 54.91 270 top
R502  80D6R2F-L-GP  [R402H16]  94.36 54.02 270 top
R503  100R2F-L1-GP-U  [R402H14]  93.9 52.32 270 top
R504  -  [0R0402-PAD]  101.4 20.03 180 bottom
R505  470R2F-GP  [R402H16]  99.52 20.03 0 bottom
R506  220KR2F-GP  [R402H16]  40.31 14.32 0 bottom
R601  49D9R2F-GP  [R402H16]  121.49 68.77 0 top
R602  -  [0R0402-PAD]  94.41 79.47 270 top
R603  100KR2J-1-GP  [R402H16]  133.48 76.06 270 bottom
R604  1KR2J-1-GP  [R402H16]  131.16 77.82 270 bottom
R605  1KR2J-1-GP  [R402H16]  122.32 76.9 0 top
R702  0R2J-2-GP  [R402H16]  120.9 71.47 0 top
R703  -  [0R0603-PAD]  123.04 42.36 270 top
R704  0R2J-2-GP  [R402H16]  120.06 71.47 0 top
R705  -  [0R0805-PAD]  94.38 57.09 0 top
R709  -  [0R0402-PAD]  133.45 71.75 270 bottom
R719  100R2F-L1-GP-U  [R402H14]  123.54 57.14 0 top
R720  100R2F-L1-GP-U  [R402H14]  122.45 55.21 270 top
R721  100R2F-L1-GP-U  [R402H14]  119.56 77.44 90 top
R722  100R2F-L1-GP-U  [R402H14]  120.98 77.11 0 top
R723  54D9R2F-L1-GP  [R402H16]  133.45 73.5 90 bottom
R724  100R2F-L1-GP-U  [R402H14]  115.16 71.37 270 top
R725  100R2F-L1-GP-U  [R402H14]  112.83 71.39 90 top
R726  100R2F-L1-GP-U  [R402H14]  133.48 72.64 90 bottom
R727  56R2J-4-GP  [R402H16]  133.45 74.36 90 bottom
R728  220R2J-L2-GP  [R402H16]  131.11 74.16 90 bottom
R729  100R2F-L1-GP-U  [R402H14]  111.1 69.56 270 top
R731  100R2F-L1-GP-U  [R402H14]  110.06 70.81 0 top
R732  -  [0R0402-PAD]  131.11 73.35 270 bottom
R734  100R2F-L1-GP-U  [R402H14]  123.44 48.91 90 top
R735  100R2F-L1-GP-U  [R402H14]  122.68 50.69 0 top
R801  24D9R2F-L-GP  [R402H16]  113.38 66.64 180 top
R802  10KR2J-3-GP  [R402H16]  119.71 27.4 180 bottom
R803  100KR2J-1-GP  [R402H16]  123.67 25.11 0 bottom
R804  0R2J-2-GP  [R402H16]  122.38 27.37 180 bottom
R1101  -  [0R1206-PAD]  93.78 17.14 0 bottom
R1102  -  [0R0603-PAD]  120.98 35.86 270 top
R1103  -  [0R0603-PAD]  108.68 37.81 90 top
R1104  -  [0R0603-PAD]  111.63 37 270 top
R1204  10KR2F-L1-GP  [R402H15]  68.38 22.44 90 top
R1205  -  [0R0402-PAD]  66.65 22.44 270 top
R1206  2R2F-GP  [R402H16]  72.62 48.04 90 top
R1208  10KR2F-L1-GP  [R402H15]  68.38 21.63 90 top
R1209  24D9R2F-L-GP  [R402H16]  72.6 49.81 90 top
R1210  -  [0R0402-PAD]  66.19 20.08 270 top
R1211  10KR2F-L1-GP  [R402H15]  62.3 44.34 270 top
R1212  -  [0R0402-PAD]  64.03 44.31 90 top
R1215  240R2F-1-GP  [R402H16]  64.08 52.59 0 top
R1216  SC2D2U10V3KX-L-GP  [C603H36]  50.95 26.74 270 top
R1302  10KR2F-L1-GP  [R402H15]  54.84 22.52 90 top
R1303  -  [0R0402-PAD]  53.11 22.52 270 top
R1305  2R2F-GP  [R402H16]  50.85 43.15 270 top
R1306  10KR2F-2-GP  [R402H16]  55.8 24.07 90 top
R1307  0R2J-L-GP  [R402H15]  54.05 24.1 270 top
R1309  24D9R2F-L-GP  [R402H16]  50.6 45.05 270 top
R1310  10KR2F-L1-GP  [R402H15]  48.46 46.4 180 top
R1311  -  [0R0402-PAD]  49.76 45.94 90 top
R1312  240R2F-1-GP  [R402H16]  51.31 55.87 270 top
R1501  100R2F-L1-GP-U  [R402H14]  123.32 43.98 270 top
R1502  200R2F-L-GP  [R402H16]  108.33 36.8 90 top
R1503  10KR2J-3-GP  [R402H16]  130.48 36.34 270 bottom
R1603  113R2F-GP  [R402H16]  114.93 38.6 90 top
R1604  100R2F-L1-GP-U  [R402H14]  122.68 38.8 90 top
R1606  10KR2J-3-GP  [R402H16]  121.49 27.4 0 bottom
R1607  10KR2J-3-GP  [R402H16]  89.43 22.93 270 top
R1608  10KR2J-3-GP  [R402H16]  120.6 27.4 0 bottom
R1701  10KR2J-3-GP  [R402H16]  117.42 43.25 90 top
R1702  1KR2J-1-GP  [R402H16]  67.99 10.13 270 top
R1704  0R2J-2-GP  [R402H16]  102.82 17.44 270 bottom
R1706  -  [0R0402-PAD]  102.82 18.25 90 bottom
R1707  10KR2J-3-GP  [R402H16]  60.63 7.71 180 bottom
R1708  0R2J-2-GP  [R402H16]  111.53 24.68 90 bottom
R1711  -  [0R0603-PAD]  60.37 9.41 270 bottom
R1713  -  [0R0402-PAD]  113.56 23.74 90 bottom
R1714  10KR2J-3-GP  [R402H16]  133.04 77.33 0 bottom
R1715  100KR2J-1-GP  [R402H16]  114.91 23.18 180 bottom
R1716  100KR2F-L1-GP  [R402H16]  64.31 6.19 270 bottom
R1717  10KR2J-3-GP  [R402H16]  123.47 37.13 270 top
R1718  0R2J-2-GP  [R402H16]  104.49 17.9 270 bottom
R1719  47KR2F-GP  [R402H16]  66.09 6.19 270 bottom
R1720  0R2J-2-GP  [R402H16]  67.99 11.9 90 top
R1722  100KR2J-1-GP  [R402H16]  63.3 7.71 180 bottom
R1724  -  [0R0805-PAD]  93.57 13.28 0 bottom
R1726  10KR2J-3-GP  [R402H16]  70.41 9.54 90 top
R1727  100KR2J-1-GP  [R402H16]  70.41 8.65 270 top
R1728  0R2J-2-GP  [R402H16]  68.45 8.7 180 top
R1729  0R2J-2-GP  [R402H16]  68.12 7.46 270 top
R1730  330KR2J-L1-GP  [R402H16]  96.24 22.62 180 top
R1731  20KR2J-L2-GP  [R402H16]  110.69 40.66 180 top
R1732  -  [0R0402-PAD]  61.44 7.71 180 bottom
R1733  0R2J-2-GP  [R402H16]  57.33 5.43 90 top
R1735  -  [0R0805-PAD]  95.38 13.28 0 bottom
R1737  100KR2J-1-GP  [R402H16]  70.56 11.27 0 top
R1801  -  [0R0402-PAD]  90.57 40.71 180 top
R1802  1MR2J-1-GP  [R402H16]  131.42 51.3 90 bottom
R1803  2K7R2F-GP  [R402H16]  123.62 59.27 0 top
R1804  22R2J-2-GP  [R402H16]  91.51 26.66 0 top
R1805  22R2J-2-GP  [R402H16]  91.51 28.34 180 top
R1810  -  [0R0402-PAD]  131.42 50.44 270 bottom
R1811  10R2F-L-GP  [R402H14]  94.44 28.64 90 top
R1812  -  [0R0402-PAD]  94.44 27.65 90 top
R1813  -  [0R0402-PAD]  94.38 49.45 270 top
R1814  10KR2J-3-GP  [R402H16]  90.7 24.1 180 top
R1815  10MR2J-L-GP  [R402H16]  99.52 22.85 180 bottom
R1816  10KR2J-3-GP  [R402H16]  67.74 2.48 270 bottom
R1818  8K2R2F-1-GP  [R402H16]  109.04 25.8 0 bottom
R1819  -  [0R0402-PAD]  110.29 26.2 270 bottom
R1820  10KR2J-3-GP  [R402H16]  97.94 22.37 180 top
R1821  10KR2J-3-GP  [R402H16]  97.1 22.39 180 top
R1822  1KR2J-1-GP  [R402H16]  113.79 25.7 90 bottom
R1823  1KR2J-1-GP  [R402H16]  112.11 25.49 90 bottom
R1824  1KR2J-1-GP  [R402H16]  94.89 33.8 180 top
R1825  1KR2J-1-GP  [R402H16]  94.46 32.53 90 top
R1836  2K2R2J-2-GP  [R402H16]  114.88 24.88 270 bottom
R1837  150KR2J-GP  [R402H16]  91.62 24.98 180 top
R1901  200R2F-L-GP  [R402H16]  115.28 39.46 90 top
R1908  -  [0R0402-PAD]  93.62 46.83 90 top
R1909  1KR2J-1-GP  [R402H16]  92.63 49.67 90 top
R1911  -  [0R0402-PAD]  93.67 45.15 90 top
R2003  0R2J-2-GP  [R402H16]  110.64 27.6 0 bottom
R2004  0R2J-2-GP  [R402H16]  109.83 27.6 0 bottom
R2005  10KR2J-3-GP  [R402H16]  110.59 29.43 180 bottom
R2006  1KR2J-1-GP  [R402H16]  92.56 38.4 0 top
R2007  1KR2J-1-GP  [R402H16]  110.21 19.8 0 bottom
R2008  10KR2J-3-GP  [R402H16]  109.75 29.43 0 bottom
R2009  10KR2J-3-GP  [R402H16]  113.28 32.12 270 bottom
R2010  10KR2J-3-GP  [R402H16]  113.71 30.88 0 bottom
R2019  1KR2J-1-GP  [R402H16]  111.1 19.8 180 bottom
R2020  0R2J-2-GP  [R402H16]  116.91 24.6 180 bottom
R2021  0R2J-2-GP  [R402H16]  117.78 24.6 180 bottom
R2022  -  [0R0402-PAD]  94.08 22.39 90 top
R2023  -  [0R0402-PAD]  94.49 23.28 90 top
R2024  -  [0R0402-PAD]  94.79 24.1 90 top
R2025  -  [0R0402-PAD]  94.84 25.72 90 top
R2026  -  [0R0402-PAD]  94.79 24.91 90 top
R2027  -  [0R0402-PAD]  94.84 26.53 90 top
R2028  -  [0R0402-PAD]  102.28 20.03 180 bottom
R2029  10KR2J-3-GP  [R402H16]  110.34 31.13 0 bottom
